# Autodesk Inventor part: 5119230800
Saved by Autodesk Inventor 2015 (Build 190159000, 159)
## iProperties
Created: 2020-07
Part Number: 5119230800
Checked By: TraceParts S.A.
Material: Generic
Catalog Web Link: www.traceparts.com
Document SubType Name: Modeling
Designer: TraceParts
Density: 1 g/cm^3
Appearance: Default
Company: TraceParts S.A.
Author: TraceParts
REFERENCE: 5119230800
DESIGN: HIT-1000 P 0,75KW (230/400V 50HZ) - 5119230800
SUPPLIER: Soler & Palau
TraceParts.PartNumber: 10-20122018-119595
TraceParts.PartTitle: HIB-P/HIT-P
TraceParts.InstanceId: 10-20122018-11959521PWKDNSY0YAPU8GQ3FBUKZNF
TraceParts.PartStatus: Published
TraceParts.PartVersion: 1.0.2
TRACEPARTS: TRACEPARTS
TraceParts.PartLanguage: en
TraceParts.ClassPath: SOLER_PALAU:10-20122018-119595
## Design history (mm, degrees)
feature "5119230800"
body "Solid1"
